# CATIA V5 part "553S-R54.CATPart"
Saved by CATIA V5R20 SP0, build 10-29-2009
Part number: 553S-R54
Definition: NONE
Nomenclature: 553S-R54
Source: Unknown
Description: 553S-R54
Bounding box of the stored display mesh (mm): x -28.75 to 28.75, y -30.5 to 30.496, z -1 to 1
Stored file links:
  C:\Users\Utente\Desktop\IO LAVORO\3D X SITO CF\X SITO\PLASTICA\553S\553S-R54.CATPart
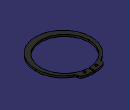
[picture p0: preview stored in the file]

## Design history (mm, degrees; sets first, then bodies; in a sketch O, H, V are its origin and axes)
Body1 "553S-R54" (main body)
  Solid1: solid without history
